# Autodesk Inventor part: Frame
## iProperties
Shininess: 64.0
Length Units: 11269
Angle Units: 11279
Time Units: 11290
Mass Units: 11283
Length Display Precision: 3
Angle Display Precision: 2
Compacted: True
Part Number: Frame
Document SubType Name: Modeling
Created: 2003-02
Material: Standard
Designer: hofer_a
Density: 0.0
Volumn: 0.0
Area: 0.0
PropertySet Name: Model Information
Control State: 0
Master: False
Checked Out: False
Author: hofer_a
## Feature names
1. Extrusion1
2. Bohrung1 [Hole]
3. Extrusion2
4. Extrusion3
5. Extrusion4
6. Rundung1 [Fillet]
7. Extrusion5
8. Bohrung2 [Hole]
9. Extrusion6
10. Extrusion7
